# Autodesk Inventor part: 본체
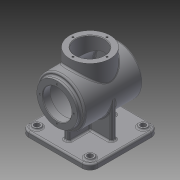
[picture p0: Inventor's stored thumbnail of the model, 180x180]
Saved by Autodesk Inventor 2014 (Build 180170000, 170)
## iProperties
Created: 2015-07
Part Number: 본체
Material: 일반
Document SubType Name: Modeling
Designer: basic
Density: 1 g/cm^3
Appearance: 기본값
Author: basic
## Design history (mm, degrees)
sketch "스케치1"
  geometry: L1 (-65, 65)-(65, 65); L2 (65, 65)-(65, -65); L3 (65, -65)-(-65, -65); L4 (-65, -65)-(-65, 65); L5 (-65, 65)-(65, -65); 2 further points
  constraints: 10 end point, 2 parallel, 1 coincident, 1 horizontal, 1 midpoint, 1 perpendicular
  dimensions: "d0" = 130 distance of L1.start L1.end; "d1" = 130 distance of L1.end L2.end
extrude "돌출1" new body sketch "스케치1" distance "d2" = 10; taper "d3" = 0 deg
fillet "모깎기1" dims "d4" = 15
fillet "모깎기2" dims "d5" = 3
sketch "스케치2"
  geometry: C1 r 7.5 at (-50, 50); 1 further point
  constraints: 1 centre point
  dimensions: "d6" = 50 horizontal distance of point (0, 0) C1.centre; "d7" = 50 horizontal distance of C1.centre point (0, 0); "d8" = 15 diameter of C1
extrude "돌출2" join sketch "스케치2" distance "d9" = 3; taper "d10" = 0 deg
sketch "스케치3"
  geometry: C1 r 7.5 at (0, 0) reference; C2 r 5 at (0, 0); 1 further point
  constraints: 1 centre point, 1 coincident
  dimensions: "d11" = 10 diameter of C2
extrude "돌출3" cut sketch "스케치3" stored distance "d12" = 3; taper "d13" = 0 deg
fillet "모깎기3" dims "d14" = 3
sketch "스케치4"
  geometry: L1 (-62, 10)-(62, 10) reference; L2 (65, 7)-(65, 0) reference; L3 (65, 0)-(-65, 0) reference; L4 (-65, 0)-(-65, 7) reference; L5 (0, 0)-(0, 78); C1 r 45 at (0, 78); A1 r 3 centre (62, 7) between (65, 7) and (62, 10) reference; A2 r 3 centre (-62, 7) between (-62, 10) and (-65, 7) reference
  constraints: 2 end point, 1 centre point, 1 coincident, 1 parallel
  dimensions: "d15" = 78 distance of L5.start L5.end; "d16" = 90 diameter of C1
extrude "돌출4" join sketch "스케치4" stored distance "d17" = 110; taper "d18" = 0 deg
sketch "스케치5"
  geometry: C1 r 45 at (0, 0) reference; C2 r 38 at (0, 0); 1 further point
  constraints: 1 centre point, 1 coincident
  dimensions: "d19" = 76 diameter of C2
extrude "돌출5" join sketch "스케치5" distance "d20" = 7; taper "d21" = 0 deg
sketch "스케치6"
  geometry: C1 r 38 at (0, 0) reference; 2 further points
  constraints: 1 vertical alignment
  dimensions: "d22" = 32 distance of C1.centre point (0, 32)
hole "구멍1" sketch "스케치6" at (0, 32) diameter "d23" = 3.242; stored, may be unused: countersink angle "d27" = 90 deg, drill point angle "d29" = 118 deg; dims "d24" = 8, "d25" = 4, "d26" = 2, "d28" = 10
sketch "스케치7"
  geometry: C1 r 38 at (0, 0) reference; C2 r 27 at (0, 0); 1 further point
  constraints: 1 centre point, 1 coincident
  dimensions: "d33" = 54 diameter of C2
extrude "돌출6" cut sketch "스케치7" distance "d34" = 14; taper "d35" = 0 deg
sketch "스케치8"
  geometry: C1 r 27 at (0, 0) reference; C2 r 40 at (0, 0); 1 further point
  constraints: 1 centre point, 1 coincident
  dimensions: "d36" = 80 diameter of C2
extrude "돌출7" cut sketch "스케치8" distance "d37" = 96; taper "d38" = 0 deg
node "작업 평면1"
sketch "스케치9"
  geometry: C1 r 38 at (0, 0); 1 further point
  constraints: 1 centre point, 1 coincident
  dimensions: "d40" = 76 diameter of C1
extrude "돌출8" join sketch "스케치9" stored distance "d41" = 96; taper "d42" = 0 deg
sketch "스케치10"
  geometry: C1 r 38 at (0, 0) reference; C2 r 27 at (0, 0)
  constraints: 1 centre point, 1 coincident
  dimensions: "d43" = 54 diameter of C2
extrude "돌출9" cut sketch "스케치10" stored distance "d44" = 96; taper "d45" = 0 deg
sketch "스케치11"
  geometry: C1 r 27 at (0, 0) reference; 1 further point
  constraints: 1 vertical alignment
  dimensions: "d46" = 32 distance of C1.centre point (0, 32)
hole "구멍2" sketch "스케치11" at (0, 32) diameter "d47" = 3.242; stored, may be unused: countersink angle "d51" = 90 deg, drill point angle "d53" = 118 deg; dims "d48" = 8, "d49" = 4, "d50" = 2, "d52" = 10
sketch "스케치12"
  geometry: L1 (-5, 45)-(5, 45); L2 (5, 45)-(5, -45); L3 (5, -45)-(-5, -45); L4 (-5, -45)-(-5, 45); L5 (-5, 45)-(5, -45); L6 (-45, 5)-(45, 5); L7 (45, 5)-(45, -5); L8 (45, -5)-(-45, -5); L9 (-45, -5)-(-45, 5); L10 (-45, 5)-(45, -5); 2 further points
  constraints: 20 end point, 4 parallel, 2 horizontal, 2 midpoint, 2 perpendicular, 1 coincident
  dimensions: "d57" = 10 distance between parallel lines of L2 L4; "d58" = 90 distance between parallel lines of L3 L1; "d61" = 10 distance of L6.end L7.end; "d62" = 90 distance of L7.end L8.end
extrude "돌출11" join sketch "스케치12" stored distance "d63" = 10; taper "d64" = 0 deg
fillet "모깎기4" dims "d65" = 3
fillet "모깎기5" dims "d66" = 3
fillet "모깎기6" dims "d67" = 3
fillet "모깎기7" dims "d68" = 3
chamfer "모따기1" distance "d69" = 1; stored, may be unused: second distance "d70" = 2, angle "d71" = 45 deg
sketch "스케치13" dims "d0" = 130, "d1" = 130
  geometry: C1 r 42 at (0, 0) reference; 2 further points
  constraints: 1 coincident, 1 other
feature "엠보싱1" sketch "스케치13" dims "d0" = 130, "d1" = 130, "d72" = 0.5, "d73" = 0
node "솔리드1"
mirror "대칭1"
mirror "대칭2"
pattern_circular "원형 패턴1" dims angle "d31" = 360 deg
pattern_circular "원형 패턴2" dims angle "d55" = 360 deg
node "절단 모서리 투영1"
